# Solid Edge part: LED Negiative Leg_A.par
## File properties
Title: LED Negiative Leg
Author: NMH
Template: iso metric part.par
Last saved by: NMH
Revision: 4
Application: Solid Edge
Accuracy: 0.990
Rev B: B
Rev B Text: -
Rev B Date: -
Rev C: C
Rev C Text: -
Rev C Date: -
Rev D: D
Rev D Text: -
Rev D Date: -
Part Number: -
Profile: -
Casting: -
Username: NMH
Document Number: N
Revision: A
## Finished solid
Body 1: solid body, 19 faces, 51 edges, 34 vertices.
  Faces by surface: plane 13, cylinder 6
  Edges by curve: line 39, circle 12
Bounding box of the edges (mm): 2.316 x 0.410 x 20.000, from (-0.505, -0.205, -18) to (1.8107, 0.205, 2).
Cylindrical faces by radius (mm): R0.1 x4, R0.2 x1, R0.41 x1
Planar faces by outward normal: +x 3, +y 1, +z 1, -x 4, -y 1, -z 2, oblique 1
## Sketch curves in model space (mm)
line (3.35, -0.205, -1.9) -> (-1.96, -0.205, -1.9)
line (0.095, -0.205, -4.6) -> (-0.505, -0.205, -4.6)
line (-0.505, -0.205, -5.8) -> (0.095, -0.205, -5.8)
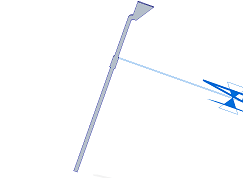
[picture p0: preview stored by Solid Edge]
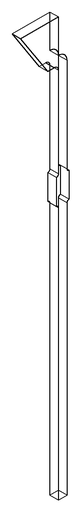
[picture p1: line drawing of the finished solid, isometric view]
